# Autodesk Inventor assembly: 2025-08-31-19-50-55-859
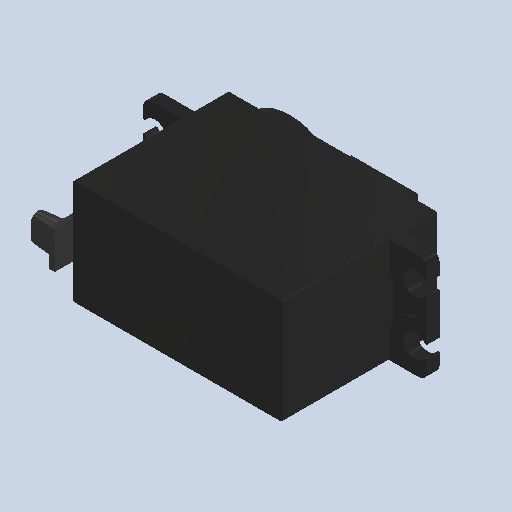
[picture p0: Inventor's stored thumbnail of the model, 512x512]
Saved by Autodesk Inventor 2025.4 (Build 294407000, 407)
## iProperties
Created: 2026-09
Part Number: 2025-08-31-19-50-55-859
Document SubType Name: Assembly
Designer: AdminForWorker
Title: com_top
Author: AdminForWorker
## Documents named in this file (3)
- c:\worker\convert-fusion-r05-cosv3\tmp\job-1\19\temp\files\ca3d996b-dda0-445d-8bee-12a194174ca8\com_top.iam
- c:\worker\convert-fusion-r05-cosv3\tmp\job-1\19\temp\files\ca3d996b-dda0-445d-8bee-12a194174ca8\Component8.ipt
- c:\worker\convert-fusion-r05-cosv3\tmp\job-1\19\temp\files\ca3d996b-dda0-445d-8bee-12a194174ca8\Part4.ipt
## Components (2 placed, 2 different names)
1. Component8:1
2. Part4
